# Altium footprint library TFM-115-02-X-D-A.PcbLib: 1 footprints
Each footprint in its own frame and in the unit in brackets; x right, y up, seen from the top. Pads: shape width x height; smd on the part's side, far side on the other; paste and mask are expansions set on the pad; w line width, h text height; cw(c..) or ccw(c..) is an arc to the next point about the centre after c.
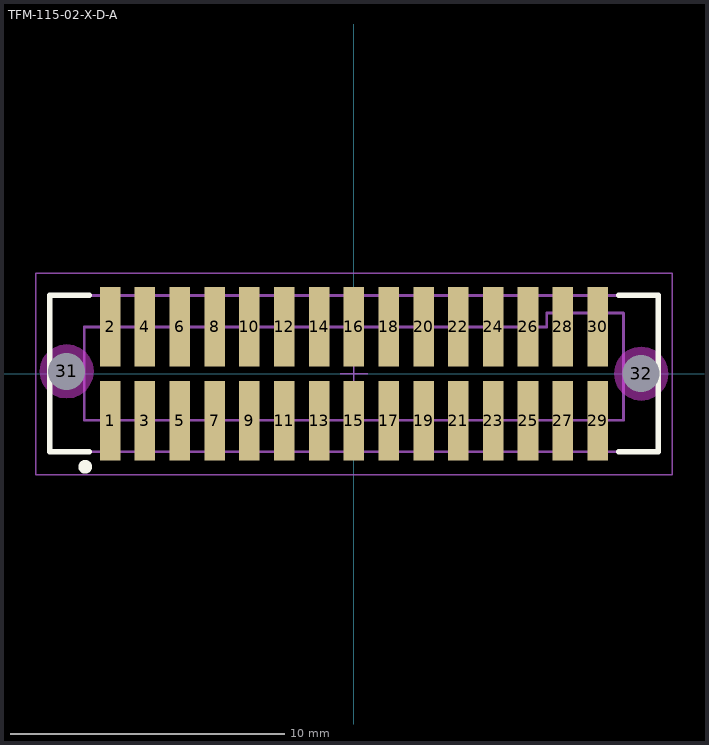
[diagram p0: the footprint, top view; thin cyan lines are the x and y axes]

## TFM-115-02-X-D-A [mm] "1.27mm pitch, 30 pin, terminal strip; w/alignment pins, SMT"
height 5.59
pads (32):
  rect 0.75x2.9 smd mask+0: 1(-8.89,-1.714) 2(-8.89,1.714) 3(-7.62,-1.714) 4(-7.62,1.714) 5(-6.35,-1.714) 6(-6.35,1.714) 7(-5.08,-1.714) 8(-5.08,1.714) 9(-3.81,-1.714) 10(-3.81,1.714) 11(-2.54,-1.714) 12(-2.54,1.714) 13(-1.27,-1.714) 14(-1.27,1.714) 15(0,-1.714) 16(0,1.714) 17(1.27,-1.714) 18(1.27,1.714) 19(2.54,-1.714) 20(2.54,1.714) 21(3.81,-1.714) 22(3.81,1.714) 23(5.08,-1.714) 24(5.08,1.714) 25(6.35,-1.714) 26(6.35,1.714) 27(7.62,-1.714) 28(7.62,1.714) 29(8.89,-1.714) 30(8.89,1.714)
  round 1 hole 1.35 unplated mask+0: 31(-10.477,0.076) 32(10.477,0)
Top Overlay:
  circle w0.25: c-9.8,-3.4 r0.125
  lines w0.2: -9.65,-2.85 -11.1,-2.85 -11.1,2.85 -9.65,2.85 ; 9.65,-2.85 11.1,-2.85 11.1,2.85 9.65,2.85
Keep-Out Layer:
  pour cut-out: 11.461,0 11.428,0.255 11.329,0.492 11.173,0.695 10.969,0.852 10.732,0.95 10.478,0.983 10.223,0.95 9.986,0.852 9.782,0.695 9.626,0.492 9.528,0.255 9.494,0 9.528,-0.255 9.626,-0.492 9.782,-0.695 9.986,-0.852 10.223,-0.95 10.478,-0.983 10.732,-0.95 10.969,-0.852 11.173,-0.695 11.329,-0.492 11.428,-0.255
  pour cut-out: -9.494,0.076 -9.528,0.331 -9.626,0.568 -9.782,0.772 -9.986,0.928 -10.223,1.026 -10.478,1.06 -10.732,1.026 -10.969,0.928 -11.173,0.772 -11.329,0.568 -11.428,0.331 -11.461,0.076 -11.428,-0.178 -11.329,-0.415 -11.173,-0.619 -10.969,-0.775 -10.732,-0.874 -10.478,-0.907 -10.223,-0.874 -9.986,-0.775 -9.782,-0.619 -9.626,-0.415 -9.528,-0.178
Mechanical 12:
  lines w0.001: -11.1,-2.85 -11.1,2.85 11.1,2.85 11.1,-2.85 -11.1,-2.85 ; -9.83,-1.702 -9.83,1.702 7.036,1.702 7.036,2.21 9.83,2.21 9.83,-1.702 -9.83,-1.702
Mechanical 13:
  lines w0.1: -11.1,-2.85 -11.1,2.85 11.1,2.85 11.1,-2.85 -11.1,-2.85 ; -9.83,-1.702 -9.83,1.702 7.036,1.702 7.036,2.21 9.83,2.21 9.83,-1.702 -9.83,-1.702
  text ".Designator" at 0,-0.127 h1.52
Mechanical 15:
  lines w0.05: -0.5,0 0.5,0 ; 0,-0.5 0,0.5 ; -11.6,-3.683 -11.6,3.65 11.608,3.65 11.608,-3.683 -11.6,-3.683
